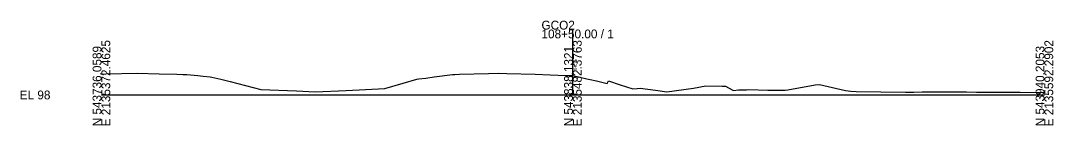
# Model space of a CAD drawing. Extents: x -14327 to 8886, y -10 to 39048.
# Drawn here: x 3974.3 to 4302.8, y 36990.3 to 37023.7 of the extents above; entities that cross this region are included whole.
import ezdxf

# ---------------------------------------------------------------- set-up
doc = ezdxf.new("R2010")
doc.units = 0
for name, color, linetype in [('RD_GPK_XS_Cell', 7, 'Continuous'), ('RD_XS_ExGround', 7, 'Continuous'), ('RD_XS_TX_Elev_EX', 7, 'Continuous')]:
    doc.layers.add(name, color=color, linetype=linetype)

msp = doc.modelspace()

# ---------------------------------------------------------------- linework, layer by layer
at = {"layer": 'RD_GPK_XS_Cell'}
for p, q in [((4150, 37000), (4150, 37020.84)), ((4000, 37000), (4150, 37000)), ((4150, 37000), (4300, 37000))]:
    msp.add_line(p, q, dxfattribs=at)
at = {"layer": 'RD_XS_ExGround'}
for p, q in [((4000, 37006.65), (4001.36, 37006.68)), ((4001.36, 37006.68), (4011.53, 37006.94)), ((4011.53, 37006.94), (4018.38, 37006.78)), ((4018.38, 37006.78), (4023.94, 37006.64)), ((4023.94, 37006.64), (4025.92, 37006.54)), ((4025.92, 37006.54), (4027.18, 37006.48)), ((4027.18, 37006.48), (4030.66, 37006.16)), ((4030.66, 37006.16), (4032.36, 37005.98)), ((4032.36, 37005.98), (4034.56, 37005.77)), ((4105.84, 37005.72), (4111.64, 37006.47)), ((4111.64, 37006.47), (4112.39, 37006.5)), ((4112.39, 37006.5), (4113.92, 37006.58)), ((4113.92, 37006.58), (4123.13, 37006.85)), ((4123.13, 37006.85), (4126.33, 37006.95)), ((4126.33, 37006.95), (4129, 37006.87)), ((4129, 37006.87), (4138.01, 37006.61)), ((4138.01, 37006.61), (4142.79, 37006.42)), ((4142.79, 37006.42), (4147.71, 37006.22)), ((4147.71, 37006.22), (4149.61, 37006.24)), ((4149.61, 37006.24), (4150, 37006.15)), ((4150, 37006.15), (4154.4, 37005.15)), ((4034.56, 37005.77), (4035.1, 37005.62)), ((4035.1, 37005.62), (4037.97, 37005.02)), ((4037.97, 37005.02), (4040.98, 37004.24)), ((4040.98, 37004.24), (4050.75, 37001.74)), ((4090.13, 37002.02), (4095.99, 37003.75)), ((4095.99, 37003.75), (4100.38, 37005.05)), ((4100.38, 37005.05), (4101.03, 37005.18)), ((4101.03, 37005.18), (4103.17, 37005.4)), ((4103.17, 37005.4), (4105.84, 37005.72)), ((4154.4, 37005.15), (4155.54, 37004.92)), ((4155.54, 37004.92), (4157.48, 37004.5)), ((4157.48, 37004.5), (4160.89, 37003.67)), ((4160.89, 37003.67), (4161.37, 37004.46)), ((4161.37, 37004.46), (4164.98, 37003.27)), ((4164.98, 37003.27), (4169.08, 37001.9)), ((4188.39, 37002.21), (4192.24, 37002.88)), ((4192.24, 37002.88), (4197.48, 37002.77)), ((4197.48, 37002.77), (4198.55, 37002.76)), ((4198.55, 37002.76), (4200.66, 37001.64)), ((4218.39, 37001.66), (4227.04, 37003.24)), ((4227.04, 37003.24), (4228.4, 37003.31)), ((4228.4, 37003.31), (4236.75, 37001.43)), ((4050.75, 37001.74), (4062.05, 37001.27)), ((4062.05, 37001.27), (4068, 37001.03)), ((4068, 37001.03), (4077.87, 37001.46)), ((4077.87, 37001.46), (4090.13, 37002.02)), ((4169.08, 37001.9), (4170.39, 37002.06)), ((4170.39, 37002.06), (4171.37, 37002.2)), ((4171.37, 37002.2), (4176.32, 37001.49)), ((4176.32, 37001.49), (4179.84, 37000.99)), ((4179.84, 37000.99), (4188.39, 37002.21)), ((4200.66, 37001.64), (4201.12, 37001.41)), ((4201.12, 37001.41), (4202.71, 37001.6)), ((4202.71, 37001.6), (4203.04, 37001.58)), ((4203.04, 37001.58), (4203.55, 37001.61)), ((4203.55, 37001.61), (4205.19, 37001.67)), ((4205.19, 37001.67), (4205.94, 37001.7)), ((4205.94, 37001.7), (4212.03, 37001.51)), ((4212.03, 37001.51), (4213.91, 37001.54)), ((4213.91, 37001.54), (4215.77, 37001.5)), ((4215.77, 37001.5), (4217.53, 37001.54)), ((4217.53, 37001.54), (4218.39, 37001.66)), ((4236.75, 37001.43), (4238.41, 37001.17)), ((4238.41, 37001.17), (4240.13, 37001.12)), ((4240.13, 37001.12), (4255.85, 37000.9)), ((4255.85, 37000.9), (4258.42, 37000.91)), ((4258.42, 37000.91), (4261.16, 37001.04)), ((4261.16, 37001.04), (4275.26, 37001.03)), ((4275.26, 37001.03), (4278.44, 37000.84)), ((4278.44, 37000.84), (4282.01, 37000.9)), ((4282.01, 37000.9), (4288.44, 37000.92)), ((4288.44, 37000.92), (4292.27, 37000.93)), ((4292.27, 37000.93), (4298.45, 37000.83)), ((4298.45, 37000.83), (4300, 37000.84))]:
    msp.add_line(p, q, dxfattribs=at)

# ---------------------------------------------------------------- texts
at = {"layer": 'RD_GPK_XS_Cell'}
for s, p in [('GCO2', (4140, 37020.84)), ('108+50.00 / 1', (4140, 37018.04)), ('EL 98', (3974, 36998.6))]:
    msp.add_text(s, height=2.8, dxfattribs=at).set_placement(p)
for s, p in [('E 2135372.4625', (4002.8, 36990)), ('E 2135482.3763', (4152.8, 36990)), ('E 2135592.2902', (4302.8, 36990)), ('N 543736.0589', (4000, 36990)), ('N 543838.1321', (4150, 36990)), ('N 543940.2053', (4300, 36990))]:
    msp.add_text(s, height=2.8, rotation=90, dxfattribs=at).set_placement(p)
at = {"layer": 'RD_XS_TX_Elev_EX'}
msp.add_text('104.15', height=1, rotation=90, dxfattribs=at).set_placement((4151.25, 37007.15))

doc.saveas('drawing.dxf')
